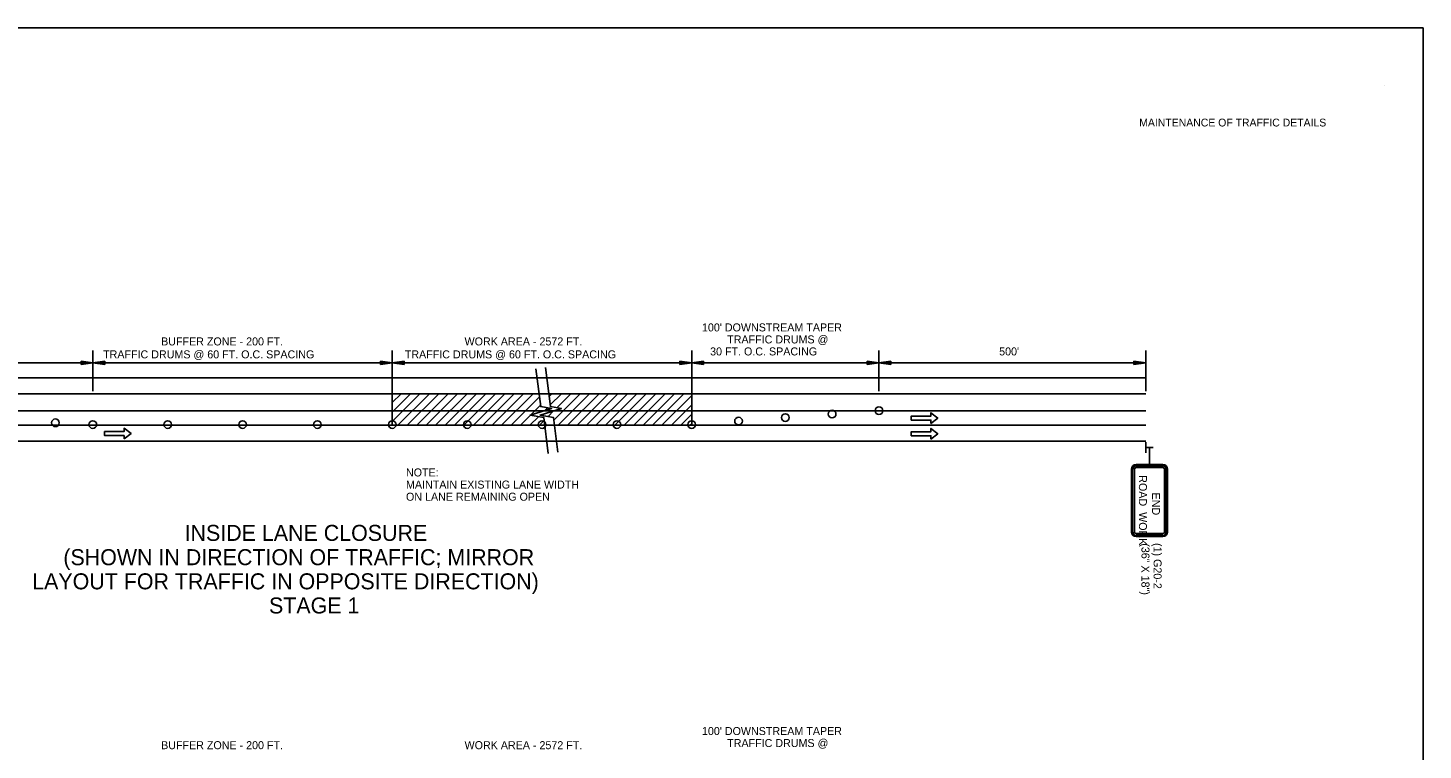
# Model space of a CAD drawing. Extents: x 1930579 to 1938013, y 596452 to 597673.
# Drawn here: x 1936967 to 1938013, y 597132 to 597673 of the extents above; entities that cross this region are included whole.
import ezdxf

# ---------------------------------------------------------------- set-up
doc = ezdxf.new("R2010")
doc.units = 0
for name, color, linetype in [('B_StampSCR', 7, 'Continuous'), ('Default', 7, 'Continuous'), ('P_TC_Signs_Temporary', 7, 'Continuous'), ('R_Annotation', 7, 'Continuous'), ('R_Border', 7, 'Continuous'), ('R_Striping', 7, 'Continuous')]:
    doc.layers.add(name, color=color, linetype=linetype)

msp = doc.modelspace()

# ---------------------------------------------------------------- linework, layer by layer
at = {"layer": 'B_StampSCR'}
msp.add_line((1937804.9, 597386.4), (1936452.7, 597386.4), dxfattribs=at)
at = {"layer": 'Default'}
for p, q in [((1937015.5, 597431.7), (1937015.5, 597401)), ((1937240, 597431.7), (1937240, 597375.6)), ((1937464.5, 597431.7), (1937464.5, 597375.6)), ((1937604.9, 597431.7), (1937604.9, 597401)), ((1937804.9, 597431.7), (1937804.9, 597401)), ((1937015.5, 597422.4), (1936791, 597422.4)), ((1937015.5, 597422.4), (1937006.7, 597423.7)), ((1937006.7, 597423.7), (1937006.7, 597421.1)), ((1937006.7, 597421.1), (1937015.5, 597422.4)), ((1937015.5, 597422.4), (1937024.4, 597423.7)), ((1937240, 597422.4), (1937015.5, 597422.4)), ((1937024.4, 597421.1), (1937015.5, 597422.4)), ((1937024.4, 597423.7), (1937024.4, 597421.1)), ((1937231.2, 597421.1), (1937231.2, 597423.7)), ((1937231.2, 597423.7), (1937240, 597422.4)), ((1937240, 597422.4), (1937231.2, 597421.1)), ((1937248.9, 597423.7), (1937240, 597422.4)), ((1937464.5, 597422.4), (1937240, 597422.4)), ((1937240, 597422.4), (1937248.9, 597421.1)), ((1937248.9, 597421.1), (1937248.9, 597423.7)), ((1937455.7, 597421.1), (1937455.7, 597423.7)), ((1937455.7, 597423.7), (1937464.5, 597422.4)), ((1937464.5, 597422.4), (1937455.7, 597421.1)), ((1937473.4, 597423.7), (1937464.5, 597422.4)), ((1937604.9, 597422.4), (1937464.5, 597422.4)), ((1937464.5, 597422.4), (1937473.4, 597421.1)), ((1937473.4, 597421.1), (1937473.4, 597423.7)), ((1937596, 597421.1), (1937596, 597423.7)), ((1937596, 597423.7), (1937604.9, 597422.4)), ((1937604.9, 597422.4), (1937596, 597421.1)), ((1937613.7, 597423.7), (1937604.9, 597422.4)), ((1937804.9, 597422.4), (1937604.9, 597422.4)), ((1937604.9, 597422.4), (1937613.7, 597421.1)), ((1937613.7, 597421.1), (1937613.7, 597423.7)), ((1937796, 597421.1), (1937796, 597423.7)), ((1937796, 597423.7), (1937804.9, 597422.4)), ((1937804.9, 597422.4), (1937796, 597421.1)), ((1937804.9, 597411.2), (1936452.7, 597411.2)), ((1937804.9, 597399.2), (1936452.7, 597399.2)), ((1937804.9, 597399.2), (1936452.7, 597399.2)), ((1937240, 597385.5), (1937253.7, 597399.2)), ((1937240, 597392.6), (1937246.6, 597399.2)), ((1937240.2, 597378.6), (1937260.7, 597399.2)), ((1937244.2, 597375.6), (1937267.8, 597399.2)), ((1937251.3, 597375.6), (1937274.9, 597399.2)), ((1937258.4, 597375.6), (1937282, 597399.2)), ((1937265.5, 597375.6), (1937289, 597399.2)), ((1937272.5, 597375.6), (1937296.1, 597399.2)), ((1937279.6, 597375.6), (1937303.2, 597399.2)), ((1937286.7, 597375.6), (1937310.2, 597399.2)), ((1937293.7, 597375.6), (1937317.3, 597399.2)), ((1937300.8, 597375.6), (1937324.4, 597399.2)), ((1937307.9, 597375.6), (1937331.5, 597399.2)), ((1937315, 597375.6), (1937338.5, 597399.2)), ((1937322, 597375.6), (1937345.6, 597399.2)), ((1937329.1, 597375.6), (1937350.4, 597396.9)), ((1937357.6, 597397.1), (1937359.7, 597399.2)), ((1937357.6, 597397.1), (1937359.7, 597399.2)), ((1937358.4, 597390.8), (1937366.8, 597399.2)), ((1937361.2, 597379.4), (1937380.9, 597399.2)), ((1937363.4, 597388.7), (1937373.9, 597399.2)), ((1937364.5, 597375.6), (1937388, 597399.2)), ((1937371.5, 597375.6), (1937395.1, 597399.2)), ((1937378.6, 597375.6), (1937402.2, 597399.2)), ((1937385.7, 597375.6), (1937409.2, 597399.2)), ((1937392.7, 597375.6), (1937416.3, 597399.2)), ((1937399.8, 597375.6), (1937423.4, 597399.2)), ((1937406.9, 597375.6), (1937430.4, 597399.2)), ((1937413.9, 597375.6), (1937437.5, 597399.2)), ((1937421, 597375.6), (1937444.6, 597399.2)), ((1937428.1, 597375.6), (1937451.7, 597399.2)), ((1937435.2, 597375.6), (1937458.7, 597399.2)), ((1937442.2, 597375.6), (1937464.5, 597397.9)), ((1937336.2, 597375.6), (1937351.1, 597390.6)), ((1937354.1, 597386.4), (1937356.3, 597388.7)), ((1937356.8, 597382.1), (1937361, 597386.3)), ((1937449.3, 597375.6), (1937464.5, 597390.8)), ((1937804.9, 597375.6), (1936452.7, 597375.6)), ((1937343.2, 597375.6), (1937349.7, 597382)), ((1937350.3, 597375.6), (1937354, 597379.2)), ((1937350.9, 597383.2), (1937350.9, 597383.3)), ((1937456.4, 597375.6), (1937464.5, 597383.8)), ((1937463.4, 597375.6), (1937464.5, 597376.7)), ((1937463.4, 597375.6), (1937464.5, 597376.7)), ((1937804.9, 597363.6), (1936452.7, 597363.6)), ((1937804.9, 597354.9), (1937804.9, 597362.9)), ((1937805, 597358.9), (1937810.4, 597358.9))]:
    msp.add_line(p, q, dxfattribs=at)
for points in [[(1937347.7, 597417.9), (1937351.3, 597389.5), (1937359.5, 597388.1), (1937343.5, 597383.2), (1937353.7, 597381.3), (1937356.9, 597354.5)], [(1937354.9, 597418.8), (1937358.6, 597389.5), (1937366.8, 597388.1), (1937350.8, 597383.2), (1937361, 597381.3), (1937364.1, 597355.4)]]:
    msp.add_lwpolyline(points, dxfattribs=at)
for centre in [(1937534.7, 597381.3), (1937569.8, 597383.9), (1937604.9, 597386.5), (1936987.5, 597377.4), (1937015.5, 597376.1), (1937071.7, 597376.1), (1937127.8, 597376.1), (1937183.9, 597376.1), (1937240, 597376.1), (1937296.2, 597376.1), (1937352.3, 597376.1), (1937408.4, 597376.1), (1937464.5, 597376.1), (1937499.6, 597378.7)]:
    msp.add_circle(centre, 2.87, dxfattribs=at)
at = {"layer": 'P_TC_Signs_Temporary'}
for p, q in [((1937794.2, 597342.7), (1937794.2, 597295.5)), ((1937795.1, 597342.7), (1937795.1, 597295.5)), ((1937796.5, 597342.7), (1937796.5, 597295.5)), ((1937817.8, 597346.1), (1937797.6, 597346.1)), ((1937817.8, 597345.2), (1937797.6, 597345.2)), ((1937817.8, 597343.9), (1937797.6, 597343.9)), ((1937819, 597295.5), (1937819, 597342.7)), ((1937820.3, 597295.5), (1937820.3, 597342.7)), ((1937821.2, 597295.5), (1937821.2, 597342.7)), ((1937797.6, 597294.4), (1937817.8, 597294.4)), ((1937797.6, 597293.1), (1937817.8, 597293.1)), ((1937797.6, 597292.1), (1937817.8, 597292.1))]:
    msp.add_line(p, q, dxfattribs=at)
for centre, radius, start, end in [((1937797.6, 597342.7), 3.38, 90, 180), ((1937797.6, 597342.7), 2.44, 90, 180), ((1937797.6, 597342.7), 1.13, 90, 180), ((1937817.8, 597342.7), 3.37, 360, 90), ((1937817.8, 597342.7), 2.44, 360, 90), ((1937817.8, 597342.7), 1.13, 360, 90), ((1937797.6, 597295.5), 3.37, 180, 270), ((1937797.6, 597295.5), 2.44, 180, 270), ((1937797.6, 597295.5), 1.13, 180, 270), ((1937817.8, 597295.5), 2.44, 270, 360), ((1937817.8, 597295.5), 1.13, 270, 360), ((1937817.8, 597295.5), 3.38, 270, 360)]:
    msp.add_arc(centre, radius, start, end, dxfattribs=at)
at = {"layer": 'R_Annotation'}
msp.add_line((1937807.7, 597358.9), (1937807.7, 597346.1), dxfattribs=at)
at = {"layer": 'R_Border'}
msp.add_line((1937984, 597629.9), (1937984, 597629.9), dxfattribs=at)
msp.add_lwpolyline([(1938012.8, 597673.4), (1936312.8, 597673.4), (1936312.8, 596573.4), (1938012.8, 596573.4)], close=True, dxfattribs=at)
at = {"layer": 'R_Striping'}
for points in [[(1937643.8, 597377), (1937649, 597381), (1937643.8, 597385), (1937643.8, 597382.5), (1937629.1, 597382.5), (1937629.1, 597379.5), (1937643.8, 597379.5)], [(1937039, 597365.3), (1937044.2, 597369.3), (1937039, 597373.3), (1937039, 597370.8), (1937024.3, 597370.8), (1937024.3, 597367.8), (1937039, 597367.8)], [(1937643.8, 597365.2), (1937649, 597369.2), (1937643.8, 597373.2), (1937643.8, 597370.7), (1937629.1, 597370.7), (1937629.1, 597367.7), (1937643.8, 597367.7)]]:
    msp.add_lwpolyline(points, close=True, dxfattribs=at)

# ---------------------------------------------------------------- texts
at = {"layer": 'Default'}
for s, height, p in [("100' DOWNSTREAM TAPER", 6, (1937472.2, 597445.9)), ('BUFFER ZONE - 200 FT.', 6, (1937066.7, 597435.4)), ('WORK AREA - 2572 FT. ', 6, (1937294.2, 597435.4)), ('TRAFFIC DRUMS @ ', 6, (1937491.1, 597436.9)), ('TRAFFIC DRUMS @ 60 FT. O.C. SPACING', 6, (1937023.2, 597425.7)), ('TRAFFIC DRUMS @ 60 FT. O.C. SPACING', 6, (1937249.4, 597425.7)), ('30 FT. O.C. SPACING', 6, (1937478.3, 597427.9)), ("500'", 6, (1937695, 597427.9)), ('INSIDE LANE CLOSURE', 12, (1937084.3, 597288.9)), ('(SHOWN IN DIRECTION OF TRAFFIC; MIRROR', 12, (1936993.4, 597270.7)), (' LAYOUT FOR TRAFFIC IN OPPOSITE DIRECTION)', 12, (1936965.6, 597252.6)), ('STAGE 1', 12, (1937147.6, 597234.5)), ("100' DOWNSTREAM TAPER", 6, (1937472.2, 597143.4)), ('BUFFER ZONE - 200 FT.', 6, (1937066.7, 597132.8)), ('WORK AREA - 2572 FT. ', 6, (1937294.2, 597132.8)), ('TRAFFIC DRUMS @ ', 6, (1937491.1, 597134.4))]:
    msp.add_text(s, height=height, rotation=360, dxfattribs=at).set_placement(p)
at = {"layer": 'P_TC_Signs_Temporary'}
for s, p in [('ROAD  WORK', (1937799.8, 597338.1)), ('END', (1937809.6, 597325.1))]:
    msp.add_text(s, height=6, rotation=270, dxfattribs=at).set_placement(p)
at = {"layer": 'R_Annotation'}
for s, rotation, p in [('NOTE:', 360, (1937250.3, 597337.2)), ('MAINTAIN EXISTING LANE WIDTH', 360, (1937250.3, 597328.1)), ('ON LANE REMAINING OPEN', 360, (1937250.3, 597319)), ('(36" X 18")', 270, (1937801.7, 597287.1)), ('(1) G20-2', 270, (1937810.8, 597287.3))]:
    msp.add_text(s, height=6, rotation=rotation, dxfattribs=at).set_placement(p)
at = {"layer": 'R_Border'}
msp.add_text('MAINTENANCE OF TRAFFIC DETAILS', height=5.862, rotation=360, dxfattribs=at).set_placement((1937800, 597599.5))

doc.saveas('drawing.dxf')
